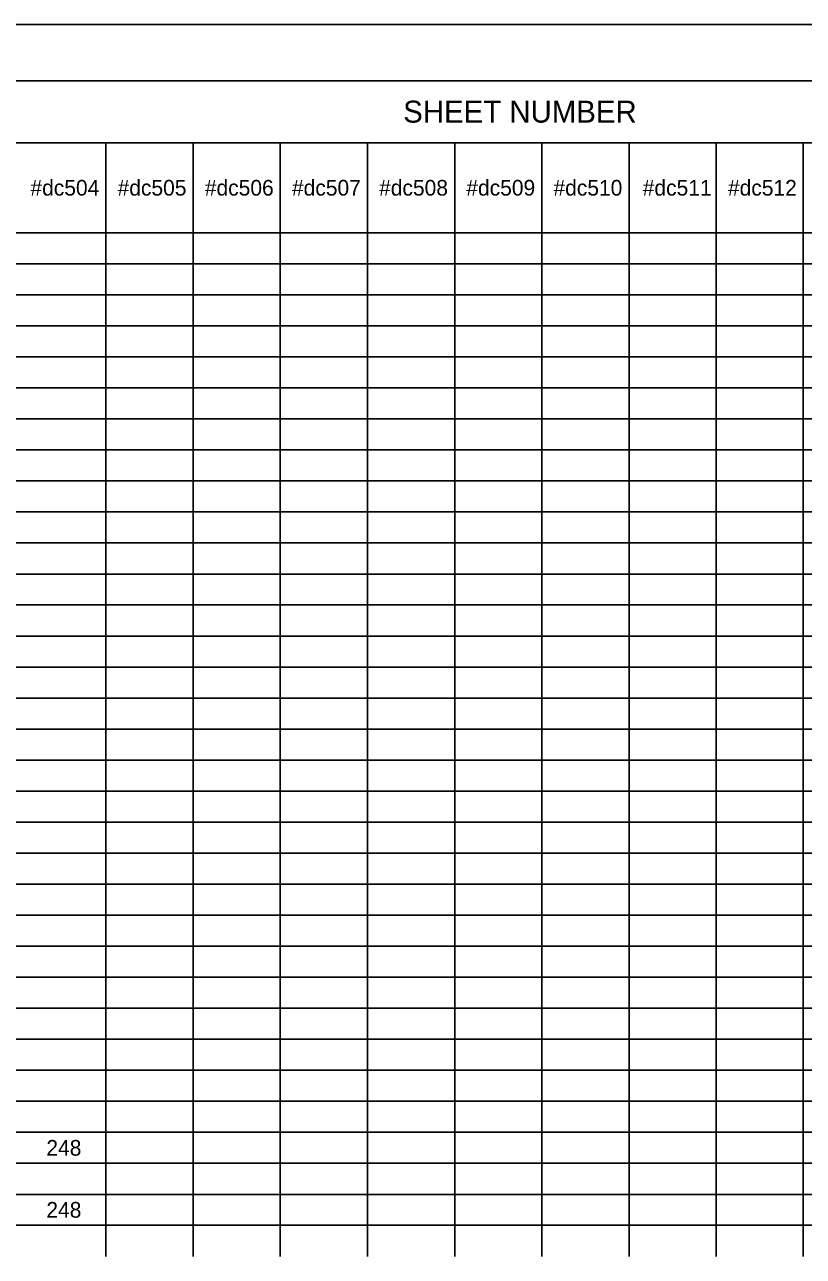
# Model space of a CAD drawing. Extents: x 0.2 to 34.2, y 0 to 22.
# Drawn here: x 6.5 to 13.45, y 11.04 to 22.03 of the extents above; entities that cross this region are included whole.
import ezdxf

# ---------------------------------------------------------------- set-up
doc = ezdxf.new("R2010")
doc.units = 0
for name, color, linetype in [('Default', 7, 'Continuous'), ('SH_Border', 7, 'Continuous'), ('SH_Cut_Line', 7, 'Continuous')]:
    doc.layers.add(name, color=color, linetype=linetype)

msp = doc.modelspace()

# ---------------------------------------------------------------- linework, layer by layer
at = {"layer": 'Default'}
for p, q in [((4.894, 21.525), (8.004, 21.525)), ((8.004, 21.525), (8.781, 21.525)), ((8.781, 21.525), (13.445, 21.525)), ((13.445, 21.525), (14.223, 21.525)), ((4.894, 20.972), (8.004, 20.972)), ((7.226, 20.972), (7.226, 20.722)), ((8.004, 20.972), (8.781, 20.972)), ((8.004, 20.972), (8.004, 20.722)), ((8.781, 20.972), (13.445, 20.972)), ((8.781, 20.972), (8.781, 20.722)), ((9.558, 20.972), (9.558, 20.722)), ((10.336, 20.972), (10.336, 20.722)), ((11.113, 20.972), (11.113, 20.722)), ((11.891, 20.972), (11.891, 20.722)), ((12.668, 20.972), (12.668, 20.722)), ((13.445, 20.972), (14.223, 20.972)), ((13.445, 20.972), (13.445, 20.722)), ((7.226, 20.722), (7.226, 20.445)), ((8.004, 20.722), (8.004, 20.445)), ((8.781, 20.722), (8.781, 20.445)), ((9.558, 20.722), (9.558, 20.445)), ((10.336, 20.722), (10.336, 20.445)), ((11.113, 20.722), (11.113, 20.445)), ((11.891, 20.722), (11.891, 20.445)), ((12.668, 20.722), (12.668, 20.445)), ((13.445, 20.722), (13.445, 20.445)), ((7.226, 20.445), (7.226, 20.168)), ((8.004, 20.445), (8.004, 20.168)), ((8.781, 20.445), (8.781, 20.168)), ((9.558, 20.445), (9.558, 20.168)), ((10.336, 20.445), (10.336, 20.168)), ((11.113, 20.445), (11.113, 20.168)), ((11.891, 20.445), (11.891, 20.168)), ((12.668, 20.445), (12.668, 20.168)), ((13.445, 20.445), (13.445, 20.168)), ((4.894, 20.168), (8.004, 20.168)), ((7.226, 20.168), (7.226, 19.891)), ((8.004, 20.168), (8.781, 20.168)), ((8.004, 20.168), (8.004, 19.891)), ((8.781, 20.168), (13.445, 20.168)), ((8.781, 20.168), (8.781, 19.891)), ((9.558, 20.168), (9.558, 19.891)), ((10.336, 20.168), (10.336, 19.891)), ((11.113, 20.168), (11.113, 19.891)), ((11.891, 20.168), (11.891, 19.891)), ((12.668, 20.168), (12.668, 19.891)), ((13.445, 20.168), (14.223, 20.168)), ((13.445, 20.168), (13.445, 19.891)), ((4.894, 19.891), (8.004, 19.891)), ((7.226, 19.891), (7.226, 19.615)), ((8.004, 19.891), (8.781, 19.891)), ((8.004, 19.891), (8.004, 19.615)), ((8.781, 19.891), (13.445, 19.891)), ((8.781, 19.891), (8.781, 19.615)), ((9.558, 19.891), (9.558, 19.615)), ((10.336, 19.891), (10.336, 19.615)), ((11.113, 19.891), (11.113, 19.615)), ((11.891, 19.891), (11.891, 19.615)), ((12.668, 19.891), (12.668, 19.615)), ((13.445, 19.891), (14.223, 19.891)), ((13.445, 19.891), (13.445, 19.615)), ((4.894, 19.615), (8.004, 19.615)), ((7.226, 19.615), (7.226, 19.338)), ((8.004, 19.615), (8.781, 19.615)), ((8.004, 19.615), (8.004, 19.338)), ((8.781, 19.615), (13.445, 19.615)), ((8.781, 19.615), (8.781, 19.338)), ((9.558, 19.615), (9.558, 19.338)), ((10.336, 19.615), (10.336, 19.338)), ((11.113, 19.615), (11.113, 19.338)), ((11.891, 19.615), (11.891, 19.338)), ((12.668, 19.615), (12.668, 19.338)), ((13.445, 19.615), (14.223, 19.615)), ((13.445, 19.615), (13.445, 19.338)), ((4.894, 19.338), (8.004, 19.338)), ((7.226, 19.338), (7.226, 19.061)), ((8.004, 19.338), (8.781, 19.338)), ((8.004, 19.338), (8.004, 19.061)), ((8.781, 19.338), (13.445, 19.338)), ((8.781, 19.338), (8.781, 19.061)), ((9.558, 19.338), (9.558, 19.061)), ((10.336, 19.338), (10.336, 19.061)), ((11.113, 19.338), (11.113, 19.061)), ((11.891, 19.338), (11.891, 19.061)), ((12.668, 19.338), (12.668, 19.061)), ((13.445, 19.338), (14.223, 19.338)), ((13.445, 19.338), (13.445, 19.061)), ((4.894, 19.061), (8.004, 19.061)), ((7.226, 19.061), (7.226, 18.785)), ((8.004, 19.061), (8.781, 19.061)), ((8.004, 19.061), (8.004, 18.785)), ((8.781, 19.061), (13.445, 19.061)), ((8.781, 19.061), (8.781, 18.785)), ((9.558, 19.061), (9.558, 18.785)), ((10.336, 19.061), (10.336, 18.785)), ((11.113, 19.061), (11.113, 18.785)), ((11.891, 19.061), (11.891, 18.785)), ((12.668, 19.061), (12.668, 18.785)), ((13.445, 19.061), (14.223, 19.061)), ((13.445, 19.061), (13.445, 18.785)), ((4.894, 18.785), (8.004, 18.785)), ((7.226, 18.785), (7.226, 18.508)), ((8.004, 18.785), (8.781, 18.785)), ((8.004, 18.785), (8.004, 18.508)), ((8.781, 18.785), (13.445, 18.785)), ((8.781, 18.785), (8.781, 18.508)), ((9.558, 18.785), (9.558, 18.508)), ((10.336, 18.785), (10.336, 18.508)), ((11.113, 18.785), (11.113, 18.508)), ((11.891, 18.785), (11.891, 18.508)), ((12.668, 18.785), (12.668, 18.508)), ((13.445, 18.785), (14.223, 18.785)), ((13.445, 18.785), (13.445, 18.508)), ((4.894, 18.508), (8.004, 18.508)), ((7.226, 18.508), (7.226, 18.231)), ((8.004, 18.508), (8.781, 18.508)), ((8.004, 18.508), (8.004, 18.231)), ((8.781, 18.508), (13.445, 18.508)), ((8.781, 18.508), (8.781, 18.231)), ((9.558, 18.508), (9.558, 18.231)), ((10.336, 18.508), (10.336, 18.231)), ((11.113, 18.508), (11.113, 18.231)), ((11.891, 18.508), (11.891, 18.231)), ((12.668, 18.508), (12.668, 18.231)), ((13.445, 18.508), (14.223, 18.508)), ((13.445, 18.508), (13.445, 18.231)), ((4.894, 18.231), (8.004, 18.231)), ((7.226, 18.231), (7.226, 17.954)), ((8.004, 18.231), (8.781, 18.231)), ((8.004, 18.231), (8.004, 17.954)), ((8.781, 18.231), (13.445, 18.231)), ((8.781, 18.231), (8.781, 17.954)), ((9.558, 18.231), (9.558, 17.954)), ((10.336, 18.231), (10.336, 17.954)), ((11.113, 18.231), (11.113, 17.954)), ((11.891, 18.231), (11.891, 17.954)), ((12.668, 18.231), (12.668, 17.954)), ((13.445, 18.231), (14.223, 18.231)), ((13.445, 18.231), (13.445, 17.954)), ((4.894, 17.954), (8.004, 17.954)), ((7.226, 17.954), (7.226, 17.678)), ((8.004, 17.954), (8.781, 17.954)), ((8.004, 17.954), (8.004, 17.678)), ((8.781, 17.954), (13.445, 17.954)), ((8.781, 17.954), (8.781, 17.678)), ((9.558, 17.954), (9.558, 17.678)), ((10.336, 17.954), (10.336, 17.678)), ((11.113, 17.954), (11.113, 17.678)), ((11.891, 17.954), (11.891, 17.678)), ((12.668, 17.954), (12.668, 17.678)), ((13.445, 17.954), (14.223, 17.954)), ((13.445, 17.954), (13.445, 17.678)), ((4.894, 17.678), (8.004, 17.678)), ((7.226, 17.678), (7.226, 17.401)), ((8.004, 17.678), (8.781, 17.678)), ((8.004, 17.678), (8.004, 17.401)), ((8.781, 17.678), (13.445, 17.678)), ((8.781, 17.678), (8.781, 17.401)), ((9.558, 17.678), (9.558, 17.401)), ((10.336, 17.678), (10.336, 17.401)), ((11.113, 17.678), (11.113, 17.401)), ((11.891, 17.678), (11.891, 17.401)), ((12.668, 17.678), (12.668, 17.401)), ((13.445, 17.678), (14.223, 17.678)), ((13.445, 17.678), (13.445, 17.401)), ((4.894, 17.401), (8.004, 17.401)), ((7.226, 17.401), (7.226, 17.124)), ((8.004, 17.401), (8.781, 17.401)), ((8.004, 17.401), (8.004, 17.124)), ((8.781, 17.401), (13.445, 17.401)), ((8.781, 17.401), (8.781, 17.124)), ((9.558, 17.401), (9.558, 17.124)), ((10.336, 17.401), (10.336, 17.124)), ((11.113, 17.401), (11.113, 17.124)), ((11.891, 17.401), (11.891, 17.124)), ((12.668, 17.401), (12.668, 17.124)), ((13.445, 17.401), (14.223, 17.401)), ((13.445, 17.401), (13.445, 17.124)), ((4.894, 17.124), (8.004, 17.124)), ((7.226, 17.124), (7.226, 16.848)), ((8.004, 17.124), (8.781, 17.124)), ((8.004, 17.124), (8.004, 16.848)), ((8.781, 17.124), (13.445, 17.124)), ((8.781, 17.124), (8.781, 16.848)), ((9.558, 17.124), (9.558, 16.848)), ((10.336, 17.124), (10.336, 16.848)), ((11.113, 17.124), (11.113, 16.848)), ((11.891, 17.124), (11.891, 16.848)), ((12.668, 17.124), (12.668, 16.848)), ((13.445, 17.124), (14.223, 17.124)), ((13.445, 17.124), (13.445, 16.848)), ((4.894, 16.848), (8.004, 16.848)), ((7.226, 16.848), (7.226, 16.571)), ((8.004, 16.848), (8.781, 16.848)), ((8.004, 16.848), (8.004, 16.571)), ((8.781, 16.848), (13.445, 16.848)), ((8.781, 16.848), (8.781, 16.571)), ((9.558, 16.848), (9.558, 16.571)), ((10.336, 16.848), (10.336, 16.571)), ((11.113, 16.848), (11.113, 16.571)), ((11.891, 16.848), (11.891, 16.571)), ((12.668, 16.848), (12.668, 16.571)), ((13.445, 16.848), (14.223, 16.848)), ((13.445, 16.848), (13.445, 16.571)), ((4.894, 16.571), (8.004, 16.571)), ((7.226, 16.571), (7.226, 16.294)), ((8.004, 16.571), (8.781, 16.571)), ((8.004, 16.571), (8.004, 16.294)), ((8.781, 16.571), (13.445, 16.571)), ((8.781, 16.571), (8.781, 16.294)), ((9.558, 16.571), (9.558, 16.294)), ((10.336, 16.571), (10.336, 16.294)), ((11.113, 16.571), (11.113, 16.294)), ((11.891, 16.571), (11.891, 16.294)), ((12.668, 16.571), (12.668, 16.294)), ((13.445, 16.571), (14.223, 16.571)), ((13.445, 16.571), (13.445, 16.294)), ((4.894, 16.294), (8.004, 16.294)), ((7.226, 16.294), (7.226, 16.018)), ((8.004, 16.294), (8.781, 16.294)), ((8.004, 16.294), (8.004, 16.018)), ((8.781, 16.294), (13.445, 16.294)), ((8.781, 16.294), (8.781, 16.018)), ((9.558, 16.294), (9.558, 16.018)), ((10.336, 16.294), (10.336, 16.018)), ((11.113, 16.294), (11.113, 16.018)), ((11.891, 16.294), (11.891, 16.018)), ((12.668, 16.294), (12.668, 16.018)), ((13.445, 16.294), (14.223, 16.294)), ((13.445, 16.294), (13.445, 16.018)), ((4.894, 16.018), (8.004, 16.018)), ((7.226, 16.018), (7.226, 15.741)), ((8.004, 16.018), (8.781, 16.018)), ((8.004, 16.018), (8.004, 15.741)), ((8.781, 16.018), (13.445, 16.018)), ((8.781, 16.018), (8.781, 15.741)), ((9.558, 16.018), (9.558, 15.741)), ((10.336, 16.018), (10.336, 15.741)), ((11.113, 16.018), (11.113, 15.741)), ((11.891, 16.018), (11.891, 15.741)), ((12.668, 16.018), (12.668, 15.741)), ((13.445, 16.018), (14.223, 16.018)), ((13.445, 16.018), (13.445, 15.741)), ((4.894, 15.741), (8.004, 15.741)), ((7.226, 15.741), (7.226, 15.464)), ((8.004, 15.741), (8.781, 15.741)), ((8.004, 15.741), (8.004, 15.464)), ((8.781, 15.741), (13.445, 15.741)), ((8.781, 15.741), (8.781, 15.464)), ((9.558, 15.741), (9.558, 15.464)), ((10.336, 15.741), (10.336, 15.464)), ((11.113, 15.741), (11.113, 15.464)), ((11.891, 15.741), (11.891, 15.464)), ((12.668, 15.741), (12.668, 15.464)), ((13.445, 15.741), (14.223, 15.741)), ((13.445, 15.741), (13.445, 15.464)), ((4.894, 15.464), (8.004, 15.464)), ((7.226, 15.464), (7.226, 15.187)), ((8.004, 15.464), (8.781, 15.464)), ((8.004, 15.464), (8.004, 15.187)), ((8.781, 15.464), (13.445, 15.464)), ((8.781, 15.464), (8.781, 15.187)), ((9.558, 15.464), (9.558, 15.187)), ((10.336, 15.464), (10.336, 15.187)), ((11.113, 15.464), (11.113, 15.187)), ((11.891, 15.464), (11.891, 15.187)), ((12.668, 15.464), (12.668, 15.187)), ((13.445, 15.464), (14.223, 15.464)), ((13.445, 15.464), (13.445, 15.187)), ((4.894, 15.187), (8.004, 15.187)), ((7.226, 15.187), (7.226, 14.911)), ((8.004, 15.187), (8.781, 15.187)), ((8.004, 15.187), (8.004, 14.911)), ((8.781, 15.187), (13.445, 15.187)), ((8.781, 15.187), (8.781, 14.911)), ((9.558, 15.187), (9.558, 14.911)), ((10.336, 15.187), (10.336, 14.911)), ((11.113, 15.187), (11.113, 14.911)), ((11.891, 15.187), (11.891, 14.911)), ((12.668, 15.187), (12.668, 14.911)), ((13.445, 15.187), (14.223, 15.187)), ((13.445, 15.187), (13.445, 14.911)), ((4.894, 14.911), (8.004, 14.911)), ((7.226, 14.911), (7.226, 14.634)), ((8.004, 14.911), (8.781, 14.911)), ((8.004, 14.911), (8.004, 14.634)), ((8.781, 14.911), (13.445, 14.911)), ((8.781, 14.911), (8.781, 14.634)), ((9.558, 14.911), (9.558, 14.634)), ((10.336, 14.911), (10.336, 14.634)), ((11.113, 14.911), (11.113, 14.634)), ((11.891, 14.911), (11.891, 14.634)), ((12.668, 14.911), (12.668, 14.634)), ((13.445, 14.911), (14.223, 14.911)), ((13.445, 14.911), (13.445, 14.634)), ((4.894, 14.634), (8.004, 14.634)), ((7.226, 14.634), (7.226, 14.357)), ((8.004, 14.634), (8.781, 14.634)), ((8.004, 14.634), (8.004, 14.357)), ((8.781, 14.634), (13.445, 14.634)), ((8.781, 14.634), (8.781, 14.357)), ((9.558, 14.634), (9.558, 14.357)), ((10.336, 14.634), (10.336, 14.357)), ((11.113, 14.634), (11.113, 14.357)), ((11.891, 14.634), (11.891, 14.357)), ((12.668, 14.634), (12.668, 14.357)), ((13.445, 14.634), (14.223, 14.634)), ((13.445, 14.634), (13.445, 14.357)), ((4.894, 14.357), (8.004, 14.357)), ((7.226, 14.357), (7.226, 14.081)), ((8.004, 14.357), (8.781, 14.357)), ((8.004, 14.357), (8.004, 14.081)), ((8.781, 14.357), (13.445, 14.357)), ((8.781, 14.357), (8.781, 14.081)), ((9.558, 14.357), (9.558, 14.081)), ((10.336, 14.357), (10.336, 14.081)), ((11.113, 14.357), (11.113, 14.081)), ((11.891, 14.357), (11.891, 14.081)), ((12.668, 14.357), (12.668, 14.081)), ((13.445, 14.357), (14.223, 14.357)), ((13.445, 14.357), (13.445, 14.081)), ((4.894, 14.081), (8.004, 14.081)), ((7.226, 14.081), (7.226, 13.804)), ((8.004, 14.081), (8.781, 14.081)), ((8.004, 14.081), (8.004, 13.804)), ((8.781, 14.081), (13.445, 14.081)), ((8.781, 14.081), (8.781, 13.804)), ((9.558, 14.081), (9.558, 13.804)), ((10.336, 14.081), (10.336, 13.804)), ((11.113, 14.081), (11.113, 13.804)), ((11.891, 14.081), (11.891, 13.804)), ((12.668, 14.081), (12.668, 13.804)), ((13.445, 14.081), (14.223, 14.081)), ((13.445, 14.081), (13.445, 13.804)), ((4.894, 13.804), (8.004, 13.804)), ((7.226, 13.804), (7.226, 13.527)), ((8.004, 13.804), (8.781, 13.804)), ((8.004, 13.804), (8.004, 13.527)), ((8.781, 13.804), (13.445, 13.804)), ((8.781, 13.804), (8.781, 13.527)), ((9.558, 13.804), (9.558, 13.527)), ((10.336, 13.804), (10.336, 13.527)), ((11.113, 13.804), (11.113, 13.527)), ((11.891, 13.804), (11.891, 13.527)), ((12.668, 13.804), (12.668, 13.527)), ((13.445, 13.804), (14.223, 13.804)), ((13.445, 13.804), (13.445, 13.527)), ((4.894, 13.527), (8.004, 13.527)), ((7.226, 13.527), (7.226, 13.25)), ((8.004, 13.527), (8.781, 13.527)), ((8.004, 13.527), (8.004, 13.25)), ((8.781, 13.527), (13.445, 13.527)), ((8.781, 13.527), (8.781, 13.25)), ((9.558, 13.527), (9.558, 13.25)), ((10.336, 13.527), (10.336, 13.25)), ((11.113, 13.527), (11.113, 13.25)), ((11.891, 13.527), (11.891, 13.25)), ((12.668, 13.527), (12.668, 13.25)), ((13.445, 13.527), (14.223, 13.527)), ((13.445, 13.527), (13.445, 13.25)), ((4.894, 13.25), (8.004, 13.25)), ((7.226, 13.25), (7.226, 12.974)), ((8.004, 13.25), (8.781, 13.25)), ((8.004, 13.25), (8.004, 12.974)), ((8.781, 13.25), (13.445, 13.25)), ((8.781, 13.25), (8.781, 12.974)), ((9.558, 13.25), (9.558, 12.974)), ((10.336, 13.25), (10.336, 12.974)), ((11.113, 13.25), (11.113, 12.974)), ((11.891, 13.25), (11.891, 12.974)), ((12.668, 13.25), (12.668, 12.974)), ((13.445, 13.25), (14.223, 13.25)), ((13.445, 13.25), (13.445, 12.974)), ((4.894, 12.974), (8.004, 12.974)), ((7.226, 12.974), (7.226, 12.697)), ((8.004, 12.974), (8.781, 12.974)), ((8.004, 12.974), (8.004, 12.697)), ((8.781, 12.974), (13.445, 12.974)), ((8.781, 12.974), (8.781, 12.697)), ((9.558, 12.974), (9.558, 12.697)), ((10.336, 12.974), (10.336, 12.697)), ((11.113, 12.974), (11.113, 12.697)), ((11.891, 12.974), (11.891, 12.697)), ((12.668, 12.974), (12.668, 12.697)), ((13.445, 12.974), (14.223, 12.974)), ((13.445, 12.974), (13.445, 12.697)), ((4.894, 12.697), (8.004, 12.697)), ((7.226, 12.697), (7.226, 12.42)), ((8.004, 12.697), (8.781, 12.697)), ((8.004, 12.697), (8.004, 12.42)), ((8.781, 12.697), (13.445, 12.697)), ((8.781, 12.697), (8.781, 12.42)), ((9.558, 12.697), (9.558, 12.42)), ((10.336, 12.697), (10.336, 12.42)), ((11.113, 12.697), (11.113, 12.42)), ((11.891, 12.697), (11.891, 12.42)), ((12.668, 12.697), (12.668, 12.42)), ((13.445, 12.697), (14.223, 12.697)), ((13.445, 12.697), (13.445, 12.42)), ((4.894, 12.42), (8.004, 12.42)), ((7.226, 12.42), (7.226, 12.144)), ((8.004, 12.42), (8.781, 12.42)), ((8.004, 12.42), (8.004, 12.144)), ((8.781, 12.42), (13.445, 12.42)), ((8.781, 12.42), (8.781, 12.144)), ((9.558, 12.42), (9.558, 12.144)), ((10.336, 12.42), (10.336, 12.144)), ((11.113, 12.42), (11.113, 12.144)), ((11.891, 12.42), (11.891, 12.144)), ((12.668, 12.42), (12.668, 12.144)), ((13.445, 12.42), (14.223, 12.42)), ((13.445, 12.42), (13.445, 12.144)), ((4.894, 12.144), (8.004, 12.144)), ((7.226, 12.144), (7.226, 11.867)), ((8.004, 12.144), (8.781, 12.144)), ((8.004, 12.144), (8.004, 11.867)), ((8.781, 12.144), (13.445, 12.144)), ((8.781, 12.144), (8.781, 11.867)), ((9.558, 12.144), (9.558, 11.867)), ((10.336, 12.144), (10.336, 11.867)), ((11.113, 12.144), (11.113, 11.867)), ((11.891, 12.144), (11.891, 11.867)), ((12.668, 12.144), (12.668, 11.867)), ((13.445, 12.144), (14.223, 12.144)), ((13.445, 12.144), (13.445, 11.867)), ((4.894, 11.867), (8.004, 11.867)), ((7.226, 11.867), (7.226, 11.59)), ((8.004, 11.867), (8.781, 11.867)), ((8.004, 11.867), (8.004, 11.59)), ((8.781, 11.867), (13.445, 11.867)), ((8.781, 11.867), (8.781, 11.59)), ((9.558, 11.867), (9.558, 11.59)), ((10.336, 11.867), (10.336, 11.59)), ((11.113, 11.867), (11.113, 11.59)), ((11.891, 11.867), (11.891, 11.59)), ((12.668, 11.867), (12.668, 11.59)), ((13.445, 11.867), (14.223, 11.867)), ((13.445, 11.867), (13.445, 11.59)), ((4.894, 11.59), (8.004, 11.59)), ((7.226, 11.59), (7.226, 11.314)), ((8.004, 11.59), (8.781, 11.59)), ((8.004, 11.59), (8.004, 11.314)), ((8.781, 11.59), (13.445, 11.59)), ((8.781, 11.59), (8.781, 11.314)), ((9.558, 11.59), (9.558, 11.314)), ((10.336, 11.59), (10.336, 11.314)), ((11.113, 11.59), (11.113, 11.314)), ((11.891, 11.59), (11.891, 11.314)), ((12.668, 11.59), (12.668, 11.314)), ((13.445, 11.59), (14.223, 11.59)), ((13.445, 11.59), (13.445, 11.314)), ((4.894, 11.314), (8.004, 11.314)), ((7.226, 11.314), (7.226, 11.037)), ((8.004, 11.314), (8.781, 11.314)), ((8.004, 11.314), (8.004, 11.037)), ((8.781, 11.314), (13.445, 11.314)), ((8.781, 11.314), (8.781, 11.037)), ((9.558, 11.314), (9.558, 11.037)), ((10.336, 11.314), (10.336, 11.037)), ((11.113, 11.314), (11.113, 11.037)), ((11.891, 11.314), (11.891, 11.037)), ((12.668, 11.314), (12.668, 11.037)), ((13.445, 11.314), (14.223, 11.314)), ((13.445, 11.314), (13.445, 11.037))]:
    msp.add_line(p, q, dxfattribs=at)
at = {"layer": 'SH_Border'}
msp.add_lwpolyline([(1.692, 21.525), (33.692, 21.525), (33.692, 0.525), (1.692, 0.525)], close=True, dxfattribs=at)
at = {"layer": 'SH_Cut_Line'}
msp.add_lwpolyline([(0.192, 0.025), (34.192, 0.025), (34.192, 22.025), (0.192, 22.025)], close=True, dxfattribs=at)

# ---------------------------------------------------------------- texts
at = {"layer": 'Default'}
for s, height, p in [('SHEET NUMBER', 0.196, (9.877, 21.151)), ('#dc504', 0.14, (6.553, 20.5)), ('#dc505', 0.14, (7.33, 20.5)), ('#dc506', 0.14, (8.108, 20.5)), ('#dc507', 0.14, (8.885, 20.5)), ('#dc508', 0.14, (9.662, 20.5)), ('#dc509', 0.14, (10.44, 20.5)), ('#dc510', 0.14, (11.217, 20.5)), ('#dc511', 0.14, (12.013, 20.5)), ('#dc512', 0.14, (12.773, 20.5)), ('248', 0.14, (6.695, 11.935)), ('248', 0.14, (6.695, 11.382))]:
    msp.add_text(s, height=height, dxfattribs=at).set_placement(p)

doc.saveas('drawing.dxf')
